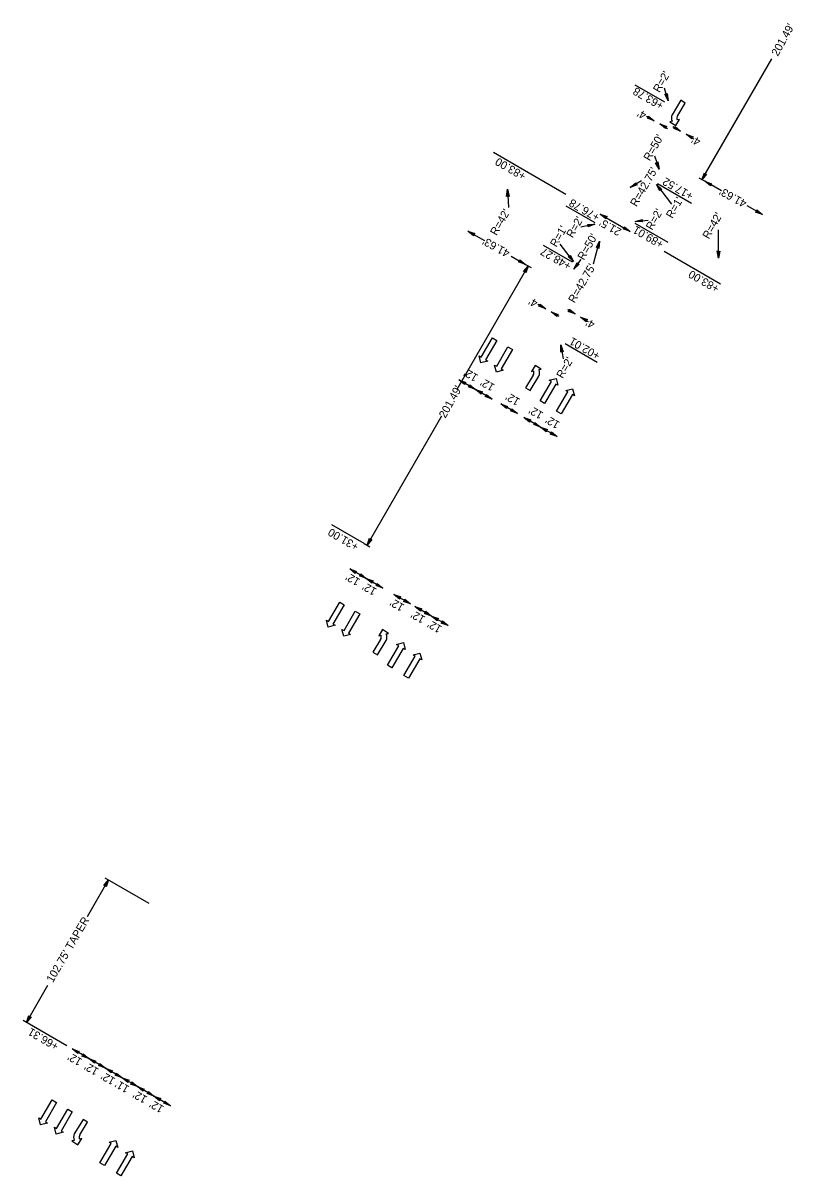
# Model space of a CAD drawing. Extents: x 2320991 to 2332664, y 598057 to 612602.
# Drawn here: x 2330205 to 2330686, y 610226 to 610947 of the extents above; entities that cross this region are included whole.
import ezdxf

# ---------------------------------------------------------------- set-up
doc = ezdxf.new("R2010")
doc.units = 0
for name, color, linetype in [('Prop Dimension', 7, 'Continuous'), ('Prop Dimension Text', 7, 'Continuous'), ('Prop Lane Arrow CELL', 7, 'Continuous'), ('Prop Terminator CELL', 7, 'Continuous')]:
    doc.layers.add(name, color=color, linetype=linetype)

msp = doc.modelspace()

# ---------------------------------------------------------------- linework, layer by layer
at = {"layer": 'Prop Dimension'}
for p, q in [((2330629.27, 610848.9), (2330672.89, 610924.38)), ((2330606.1, 610897.25), (2330587.45, 610908.03)), ((2330608.1, 610898.23), (2330605.8, 610906.12)), ((2330594.64, 610888.53), (2330599.45, 610885.75)), ((2330602.91, 610883.75), (2330607.71, 610880.97)), ((2330611.12, 610882.06), (2330615.92, 610879.28)), ((2330619.39, 610877.28), (2330624.18, 610874.51)), ((2330544.25, 610839.7), (2330498.86, 610865.93)), ((2330599.5, 610863.76), (2330602.53, 610855.49)), ((2330631, 610847.9), (2330627.53, 610849.9)), ((2330507.64, 610842.94), (2330508.28, 610831.52)), ((2330591.49, 610848.15), (2330584.38, 610844.06)), ((2330600.88, 610845.95), (2330610.3, 610833.5)), ((2330601.56, 610846.42), (2330622.81, 610834.14)), ((2330641.37, 610841.91), (2330631, 610847.9)), ((2330562.56, 610821.93), (2330544.42, 610832.41)), ((2330565.71, 610827.37), (2330584.32, 610816.61)), ((2330667.04, 610827.07), (2330657.5, 610832.59)), ((2330562.3, 610821.08), (2330553.49, 610819.24)), ((2330587.3, 610821.76), (2330607.85, 610809.88)), ((2330587.57, 610822.81), (2330595.65, 610823.58)), ((2330482.93, 610816.8), (2330493.22, 610810.85)), ((2330639.65, 610799.83), (2330639.57, 610817.59)), ((2330548.31, 610797.26), (2330530.16, 610807.75)), ((2330548.96, 610797.73), (2330540.54, 610808.69)), ((2330561.38, 610796.32), (2330565.16, 610810.57)), ((2330509.9, 610801.21), (2330518.97, 610795.96)), ((2330549.17, 610793.06), (2330553.75, 610799.01)), ((2330605.72, 610804.17), (2330640.84, 610783.87)), ((2330476.24, 610718.03), (2330520.71, 610794.96)), ((2330518.97, 610795.96), (2330522.44, 610793.96)), ((2330526.76, 610771.08), (2330531.57, 610768.3)), ((2330535.03, 610766.3), (2330539.83, 610763.52)), ((2330545.1, 610767.84), (2330549.91, 610765.06)), ((2330553.37, 610763.06), (2330558.17, 610760.29)), ((2330541.05, 610745.7), (2330542.42, 610736.86)), ((2330543.77, 610746.44), (2330563.78, 610734.87)), ((2330487.67, 610717.82), (2330477.28, 610723.83)), ((2330498.06, 610711.82), (2330487.67, 610717.82)), ((2330513.88, 610702.81), (2330503.49, 610708.81)), ((2330419.88, 610620.52), (2330466.65, 610701.44)), ((2330528.38, 610694.34), (2330518, 610700.35)), ((2330538.77, 610688.34), (2330528.38, 610694.34)), ((2330418.15, 610621.52), (2330397.87, 610633.24)), ((2330418.15, 610621.52), (2330421.63, 610619.5)), ((2330419.43, 610599.75), (2330409.04, 610605.76)), ((2330429.82, 610593.75), (2330419.43, 610599.75)), ((2330447.06, 610583.79), (2330436.67, 610589.8)), ((2330460.15, 610576.27), (2330449.76, 610582.28)), ((2330470.54, 610570.27), (2330460.15, 610576.27)), ((2330245.11, 610388.43), (2330258.35, 610411.33)), ((2330283.61, 610396.73), (2330256.27, 610412.53)), ((2330206.92, 610322.35), (2330220.42, 610345.7)), ((2330232.2, 610307.77), (2330204.86, 610323.57)), ((2330245.99, 610299.74), (2330235.6, 610305.75)), ((2330256.37, 610293.74), (2330245.99, 610299.74)), ((2330266.76, 610287.74), (2330256.37, 610293.74)), ((2330276.34, 610282.23), (2330266.81, 610287.73)), ((2330286.7, 610276.26), (2330276.31, 610282.27)), ((2330297.09, 610270.26), (2330286.7, 610276.26))]:
    msp.add_line(p, q, dxfattribs=at)
at = {"layer": 'Prop Lane Arrow CELL'}
for p, q in [((2330615.99, 610898.48), (2330610.53, 610889.46)), ((2330614.08, 610888.95), (2330618.81, 610896.78)), ((2330618.81, 610896.78), (2330615.99, 610898.48)), ((2330610.54, 610885.42), (2330609.1, 610885.06)), ((2330609.1, 610885.06), (2330612.84, 610882.74)), ((2330612.84, 610882.74), (2330615.21, 610886.57)), ((2330615.21, 610886.57), (2330613.77, 610886.21)), ((2330491.18, 610738.02), (2330498.22, 610750.12)), ((2330501.07, 610748.46), (2330494.03, 610736.36)), ((2330498.22, 610750.12), (2330501.07, 610748.46)), ((2330500.94, 610732.28), (2330507.98, 610744.38)), ((2330510.83, 610742.72), (2330503.79, 610730.62)), ((2330507.98, 610744.38), (2330510.83, 610742.72)), ((2330491.07, 610734.44), (2330489.89, 610738.77)), ((2330489.89, 610738.77), (2330491.18, 610738.02)), ((2330495.33, 610735.6), (2330491.07, 610734.44)), ((2330494.03, 610736.36), (2330495.33, 610735.6)), ((2330500.82, 610728.7), (2330499.64, 610733.03)), ((2330499.64, 610733.03), (2330500.94, 610732.28)), ((2330505.09, 610729.86), (2330500.82, 610728.7)), ((2330503.79, 610730.62), (2330505.09, 610729.86)), ((2330523.75, 610726.66), (2330519.02, 610718.83)), ((2330521.84, 610717.13), (2330527.3, 610726.15)), ((2330524.99, 610732.87), (2330522.62, 610729.04)), ((2330522.62, 610729.04), (2330524.06, 610729.4)), ((2330528.73, 610730.55), (2330524.99, 610732.87)), ((2330527.29, 610730.19), (2330528.73, 610730.55)), ((2330519.02, 610718.83), (2330521.84, 610717.13)), ((2330528.07, 610710.74), (2330535.11, 610722.84)), ((2330537.96, 610721.18), (2330530.92, 610709.08)), ((2330533.82, 610723.59), (2330538.08, 610724.76)), ((2330535.11, 610722.84), (2330533.82, 610723.59)), ((2330539.26, 610720.43), (2330537.96, 610721.18)), ((2330538.08, 610724.76), (2330539.26, 610720.43)), ((2330538.42, 610704.22), (2330545.46, 610716.32)), ((2330548.31, 610714.66), (2330541.27, 610702.56)), ((2330544.16, 610717.08), (2330548.43, 610718.24)), ((2330545.46, 610716.32), (2330544.16, 610717.08)), ((2330549.61, 610713.91), (2330548.31, 610714.66)), ((2330548.43, 610718.24), (2330549.61, 610713.91)), ((2330530.92, 610709.08), (2330528.07, 610710.74)), ((2330541.27, 610702.56), (2330538.42, 610704.22)), ((2330395.75, 610572.89), (2330402.79, 610584.99)), ((2330405.64, 610583.33), (2330398.6, 610571.23)), ((2330402.79, 610584.99), (2330405.64, 610583.33)), ((2330405.5, 610567.15), (2330412.54, 610579.25)), ((2330415.4, 610577.59), (2330408.36, 610565.49)), ((2330412.54, 610579.25), (2330415.4, 610577.59)), ((2330395.63, 610569.31), (2330394.45, 610573.64)), ((2330394.45, 610573.64), (2330395.75, 610572.89)), ((2330399.89, 610570.48), (2330395.63, 610569.31)), ((2330398.6, 610571.23), (2330399.89, 610570.48)), ((2330405.39, 610563.57), (2330404.21, 610567.91)), ((2330404.21, 610567.91), (2330405.5, 610567.15)), ((2330429.56, 610567.74), (2330427.18, 610563.92)), ((2330433.29, 610565.42), (2330429.56, 610567.74)), ((2330409.65, 610564.74), (2330405.39, 610563.57)), ((2330408.36, 610565.49), (2330409.65, 610564.74)), ((2330428.32, 610561.54), (2330423.58, 610553.71)), ((2330426.41, 610552), (2330431.86, 610561.03)), ((2330427.18, 610563.92), (2330428.63, 610564.27)), ((2330431.85, 610565.07), (2330433.29, 610565.42)), ((2330423.58, 610553.71), (2330426.41, 610552)), ((2330432.64, 610545.61), (2330439.68, 610557.72)), ((2330442.53, 610556.06), (2330435.49, 610543.95)), ((2330438.38, 610558.47), (2330442.64, 610559.63)), ((2330439.68, 610557.72), (2330438.38, 610558.47)), ((2330443.83, 610555.3), (2330442.53, 610556.06)), ((2330442.64, 610559.63), (2330443.83, 610555.3)), ((2330448.73, 610551.95), (2330452.99, 610553.12)), ((2330452.99, 610553.12), (2330454.17, 610548.79)), ((2330442.98, 610539.1), (2330450.02, 610551.2)), ((2330452.88, 610549.54), (2330445.84, 610537.44)), ((2330450.02, 610551.2), (2330448.73, 610551.95)), ((2330454.17, 610548.79), (2330452.88, 610549.54)), ((2330435.49, 610543.95), (2330432.64, 610545.61)), ((2330445.84, 610537.44), (2330442.98, 610539.1)), ((2330215.98, 610261.86), (2330223.02, 610273.96)), ((2330225.87, 610272.3), (2330218.83, 610260.2)), ((2330223.02, 610273.96), (2330225.87, 610272.3)), ((2330225.74, 610256.12), (2330232.78, 610268.22)), ((2330235.63, 610266.56), (2330228.59, 610254.46)), ((2330232.78, 610268.22), (2330235.63, 610266.56)), ((2330215.87, 610258.28), (2330214.68, 610262.61)), ((2330214.68, 610262.61), (2330215.98, 610261.86)), ((2330220.13, 610259.44), (2330215.87, 610258.28)), ((2330218.83, 610260.2), (2330220.13, 610259.44)), ((2330242.34, 610261.68), (2330236.88, 610252.65)), ((2330240.43, 610252.14), (2330245.17, 610259.97)), ((2330245.17, 610259.97), (2330242.34, 610261.68)), ((2330225.62, 610252.54), (2330224.44, 610256.87)), ((2330224.44, 610256.87), (2330225.74, 610256.12)), ((2330229.89, 610253.7), (2330225.62, 610252.54)), ((2330228.59, 610254.46), (2330229.89, 610253.7)), ((2330236.89, 610248.61), (2330235.45, 610248.26)), ((2330235.45, 610248.26), (2330239.19, 610245.94)), ((2330239.19, 610245.94), (2330241.56, 610249.76)), ((2330241.56, 610249.76), (2330240.12, 610249.41)), ((2330252.87, 610234.58), (2330259.91, 610246.68)), ((2330262.76, 610245.02), (2330255.72, 610232.92)), ((2330258.61, 610247.44), (2330262.88, 610248.6)), ((2330259.91, 610246.68), (2330258.61, 610247.44)), ((2330264.06, 610244.27), (2330262.76, 610245.02)), ((2330262.88, 610248.6), (2330264.06, 610244.27)), ((2330263.22, 610228.06), (2330270.26, 610240.16)), ((2330273.11, 610238.51), (2330266.07, 610226.4)), ((2330268.96, 610240.92), (2330273.23, 610242.08)), ((2330270.26, 610240.16), (2330268.96, 610240.92)), ((2330274.41, 610237.75), (2330273.11, 610238.51)), ((2330273.23, 610242.08), (2330274.41, 610237.75)), ((2330255.72, 610232.92), (2330252.87, 610234.58)), ((2330266.07, 610226.4), (2330263.22, 610228.06))]:
    msp.add_line(p, q, dxfattribs=at)
for centre, radius, start, end in [((2330615.37, 610887.46), 5.25, 157.51595, 202.82764), ((2330616.86, 610887.25), 3.27, 148.83987, 198.49805), ((2330520.97, 610728.36), 3.27, 328.83987, 18.49805), ((2330522.46, 610728.15), 5.25, 337.51595, 22.82764), ((2330425.53, 610563.23), 3.27, 328.83987, 18.49805), ((2330427.03, 610563.03), 5.25, 337.51595, 22.82764), ((2330241.72, 610250.65), 5.25, 157.51595, 202.82764), ((2330243.21, 610250.45), 3.27, 148.83987, 198.49805)]:
    msp.add_arc(centre, radius, start, end, dxfattribs=at)
at = {"layer": 'Prop Terminator CELL'}
for points in [[(2330607.58, 610902.77), (2330608.1, 610898.23), (2330606.07, 610902.35), (2330606.99, 610902.02)], [(2330595.94, 610888.67), (2330599.45, 610885.75), (2330595.13, 610887.32), (2330596.03, 610887.72)], [(2330606.42, 610880.82), (2330602.91, 610883.75), (2330607.23, 610882.17), (2330606.33, 610881.77)], [(2330612.42, 610882.2), (2330615.92, 610879.28), (2330611.61, 610880.85), (2330612.51, 610881.26)], [(2330622.9, 610874.35), (2330619.39, 610877.28), (2330623.71, 610875.71), (2330622.81, 610875.3)], [(2330601.71, 610859.98), (2330602.53, 610855.49), (2330600.22, 610859.46), (2330601.17, 610859.2)], [(2330632.19, 610852.41), (2330629.27, 610848.9), (2330630.84, 610853.22), (2330631.24, 610852.32)], [(2330507.12, 610838.41), (2330507.64, 610842.94), (2330508.7, 610838.47), (2330507.86, 610839)], [(2330588.67, 610845.63), (2330584.38, 610844.06), (2330587.91, 610847.01), (2330587.81, 610846.03)], [(2330602.98, 610841.89), (2330600.88, 610845.95), (2330604.25, 610842.82), (2330603.26, 610842.8)], [(2330634.5, 610844.98), (2330631, 610847.9), (2330635.31, 610846.33), (2330634.42, 610845.92)], [(2330569.22, 610824.45), (2330565.71, 610827.37), (2330570.03, 610825.8), (2330569.13, 610825.39)], [(2330663.53, 610829.99), (2330667.04, 610827.07), (2330662.72, 610828.64), (2330663.62, 610829.05)], [(2330557.74, 610820.92), (2330562.3, 610821.08), (2330558.04, 610819.37), (2330558.43, 610820.27)], [(2330580.82, 610819.53), (2330584.32, 610816.61), (2330580.01, 610818.18), (2330580.9, 610818.59)], [(2330592.12, 610822.47), (2330587.57, 610822.81), (2330592, 610824.04), (2330591.5, 610823.19)], [(2330486.44, 610813.87), (2330482.93, 610816.8), (2330487.25, 610815.22), (2330486.35, 610814.82)], [(2330563.25, 610806.42), (2330565.16, 610810.57), (2330564.77, 610805.99), (2330564.14, 610806.75)], [(2330515.47, 610798.89), (2330518.97, 610795.96), (2330514.66, 610797.54), (2330515.55, 610797.94)], [(2330546.83, 610801.77), (2330548.96, 610797.73), (2330545.57, 610800.83), (2330546.55, 610800.86)], [(2330640.4, 610804.33), (2330639.65, 610799.83), (2330638.83, 610804.35), (2330639.63, 610803.78)], [(2330517.78, 610791.46), (2330520.71, 610794.96), (2330519.13, 610790.65), (2330518.73, 610791.54)], [(2330552.53, 610796.15), (2330549.17, 610793.06), (2330551.3, 610797.13), (2330551.58, 610796.19)], [(2330528.06, 610771.22), (2330531.57, 610768.3), (2330527.25, 610769.87), (2330528.15, 610770.27)], [(2330538.54, 610763.37), (2330535.03, 610766.3), (2330539.35, 610764.72), (2330538.45, 610764.32)], [(2330546.4, 610767.98), (2330549.91, 610765.06), (2330545.59, 610766.63), (2330546.49, 610767.04)], [(2330556.88, 610760.13), (2330553.37, 610763.06), (2330557.69, 610761.49), (2330556.79, 610761.08)], [(2330540.97, 610741.13), (2330541.05, 610745.7), (2330542.53, 610741.35), (2330541.65, 610741.79)], [(2330480.79, 610720.9), (2330477.28, 610723.83), (2330481.6, 610722.25), (2330480.7, 610721.85)], [(2330484.16, 610720.74), (2330487.67, 610717.82), (2330483.35, 610719.39), (2330484.25, 610719.8)], [(2330491.18, 610714.9), (2330487.67, 610717.82), (2330491.99, 610716.25), (2330491.09, 610715.84)], [(2330494.55, 610714.74), (2330498.06, 610711.82), (2330493.74, 610713.39), (2330494.64, 610713.79)], [(2330506.99, 610705.89), (2330503.49, 610708.81), (2330507.8, 610707.24), (2330506.91, 610706.83)], [(2330510.37, 610705.73), (2330513.88, 610702.81), (2330509.56, 610704.38), (2330510.46, 610704.78)], [(2330521.5, 610697.42), (2330518, 610700.35), (2330522.31, 610698.78), (2330521.42, 610698.37)], [(2330524.88, 610697.26), (2330528.38, 610694.34), (2330524.07, 610695.91), (2330524.97, 610696.32)], [(2330531.89, 610691.42), (2330528.38, 610694.34), (2330532.7, 610692.77), (2330531.8, 610692.37)], [(2330535.27, 610691.26), (2330538.77, 610688.34), (2330534.46, 610689.91), (2330535.35, 610690.31)], [(2330422.8, 610624.02), (2330419.88, 610620.52), (2330421.45, 610624.83), (2330421.86, 610623.94)], [(2330412.55, 610602.83), (2330409.04, 610605.76), (2330413.36, 610604.18), (2330412.46, 610603.78)], [(2330415.92, 610602.67), (2330419.43, 610599.75), (2330415.11, 610601.32), (2330416.01, 610601.73)], [(2330422.94, 610596.83), (2330419.43, 610599.75), (2330423.75, 610598.18), (2330422.85, 610597.78)], [(2330426.31, 610596.67), (2330429.82, 610593.75), (2330425.5, 610595.32), (2330426.4, 610595.72)], [(2330440.18, 610586.87), (2330436.67, 610589.8), (2330440.99, 610588.22), (2330440.09, 610587.82)], [(2330443.55, 610586.71), (2330447.06, 610583.79), (2330442.74, 610585.36), (2330443.64, 610585.77)], [(2330453.26, 610579.36), (2330449.76, 610582.28), (2330454.07, 610580.71), (2330453.18, 610580.3)], [(2330456.64, 610579.2), (2330460.15, 610576.27), (2330455.83, 610577.84), (2330456.73, 610578.25)], [(2330463.65, 610573.35), (2330460.15, 610576.27), (2330464.46, 610574.7), (2330463.57, 610574.3)], [(2330467.03, 610573.19), (2330470.54, 610570.27), (2330466.22, 610571.84), (2330467.12, 610572.25)], [(2330255.43, 610407.82), (2330258.35, 610411.33), (2330256.78, 610407.01), (2330256.37, 610407.91)], [(2330209.84, 610325.86), (2330206.92, 610322.35), (2330208.49, 610326.67), (2330208.9, 610325.77)], [(2330239.1, 610302.83), (2330235.6, 610305.75), (2330239.91, 610304.18), (2330239.02, 610303.77)], [(2330242.48, 610302.67), (2330245.99, 610299.74), (2330241.67, 610301.32), (2330242.57, 610301.72)], [(2330249.49, 610296.82), (2330245.99, 610299.74), (2330250.3, 610298.17), (2330249.41, 610297.77)], [(2330252.87, 610296.66), (2330256.37, 610293.74), (2330252.06, 610295.31), (2330252.96, 610295.72)], [(2330259.88, 610290.82), (2330256.37, 610293.74), (2330260.69, 610292.17), (2330259.79, 610291.77)], [(2330263.25, 610290.66), (2330266.76, 610287.74), (2330262.44, 610289.31), (2330263.34, 610289.71)], [(2330270.32, 610284.81), (2330266.81, 610287.73), (2330271.13, 610286.16), (2330270.23, 610285.75)], [(2330272.83, 610285.15), (2330276.34, 610282.23), (2330272.02, 610283.8), (2330272.92, 610284.2)], [(2330279.82, 610279.35), (2330276.31, 610282.27), (2330280.63, 610280.7), (2330279.73, 610280.29)], [(2330283.19, 610279.19), (2330286.7, 610276.26), (2330282.38, 610277.84), (2330283.28, 610278.24)], [(2330290.21, 610273.34), (2330286.7, 610276.26), (2330291.02, 610274.69), (2330290.12, 610274.29)], [(2330293.58, 610273.18), (2330297.09, 610270.26), (2330292.77, 610271.83), (2330293.67, 610272.24)]]:
    msp.add_lwpolyline(points, close=True, dxfattribs=at)

# ---------------------------------------------------------------- texts
at = {"layer": 'Prop Dimension'}
for s, p in [('+63.78', (2330605.87, 610896.59)), ('+83.00', (2330519.75, 610852.59)), ('+17.52', (2330624.38, 610840.17)), ('+76.78', (2330565.89, 610826.84)), ('+89.01', (2330605.86, 610809.98)), ('+48.27', (2330548.05, 610796.43)), ('+83.00', (2330640.57, 610782.27)), ('+02.01', (2330566.12, 610740.33)), ('+31.00', (2330415.22, 610621.02)), ('+66.31', (2330227.67, 610308.83))]:
    msp.add_text(s, height=5, rotation=149.97374, dxfattribs=at).set_placement(p)
at = {"layer": 'Prop Dimension Text'}
for s, rotation, p in [("201.49'", 60.87983, (2330676.7, 610925.64)), ("R=2'", 59.97374, (2330602.67, 610902.92)), ("4'", 149.97374, (2330595.03, 610890.54)), ("R=50'", 59.97374, (2330596.67, 610860.18)), ("4'", 149.97374, (2330628.92, 610874.01)), ("R=42.75'", 59.97374, (2330588.35, 610831.62)), ("41.63'", 150.87983, (2330657.71, 610835.5)), ("R=1'", 59.97374, (2330610.75, 610824.29)), ("R=42'", 59.97374, (2330500.81, 610813.6)), ("R=2'", 59.97374, (2330598.13, 610816.95)), ("R=42'", 59.97374, (2330633.55, 610811.4)), ("R=1'", 59.97374, (2330538.28, 610806.37)), ("R=2'", 59.97374, (2330548.43, 610812.13)), ("21.5'", 150.21554, (2330579.38, 610817.72)), ("R=50'", 59.97374, (2330555.44, 610798.22)), ("41.63'", 150.87983, (2330509.65, 610804.4)), ("R=42.75'", 59.97374, (2330549.63, 610771.41)), ("4'", 149.97374, (2330527.15, 610773.09)), ("4'", 149.97374, (2330562.9, 610759.79)), ("R=2'", 59.97374, (2330542.21, 610724.31)), ("12'", 149.97374, (2330489.76, 610726.66)), ("201.49'", 60.87983, (2330468.84, 610699.46)), ("12'", 149.97374, (2330500.15, 610720.66)), ("12'", 149.97374, (2330515.97, 610711.65)), ("12'", 149.97374, (2330530.48, 610703.18)), ("12'", 149.97374, (2330540.87, 610697.18)), ("12'", 149.97374, (2330416.01, 610599.05)), ("12'", 149.97374, (2330426.4, 610593.04)), ("12'", 149.97374, (2330443.64, 610583.09)), ("12'", 149.97374, (2330456.72, 610575.57)), ("12'", 149.97374, (2330467.11, 610569.56)), ("102.75' TAPER", 59.7789, (2330223.44, 610346.81)), ("12'", 149.97101, (2330242.24, 610299.16)), ("12'", 149.97101, (2330252.63, 610293.15)), ("12'", 149.97101, (2330263.01, 610287.15)), ("11'", 149.97374, (2330271.78, 610282.14)), ("12'", 149.97101, (2330282.95, 610275.68)), ("12'", 149.97101, (2330293.34, 610269.67))]:
    msp.add_text(s, height=5, rotation=rotation, dxfattribs=at).set_placement(p)

doc.saveas('drawing.dxf')
